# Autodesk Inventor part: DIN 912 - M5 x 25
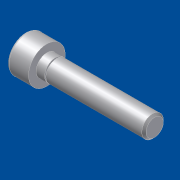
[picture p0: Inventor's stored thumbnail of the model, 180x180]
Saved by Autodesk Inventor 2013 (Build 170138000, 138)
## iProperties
Created: 2002-01
Part Number: DIN 912 - M5 x 25
Material: Standard
Catalog Web Link: file:///C:/Programme/Autodesk/Inventor%205/Content/Din/index.htm?doNavigateId=32E941FC-C430-11D4-A9F1-0080AD303E0A|0557D505B16611D4BA6900C04F798F98|true
Description: Zylinderschraube
Document SubType Name: Standard Catalog Part
Standard: DIN 912 - M5 x 25
Designer: dl
Density: 1 g/cm^3
Control State: 0
Master: False
Checked Out: False
Shininess: 20.0
Length Units: 11269
Angle Units: 11279
Time Units: 11290
Mass Units: 11283
Length Display Precision: 3
Angle Display Precision: 2
CLASSIFICATION: 31161501 un/spsc
MANUFACTURER: DIN Normsystem
Density: 0.0
Volumn: 0.0
Area: 0.0
PropertySet Name: Model Information
Author: dl
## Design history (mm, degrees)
feature "Basis1"
body "Solid1"
